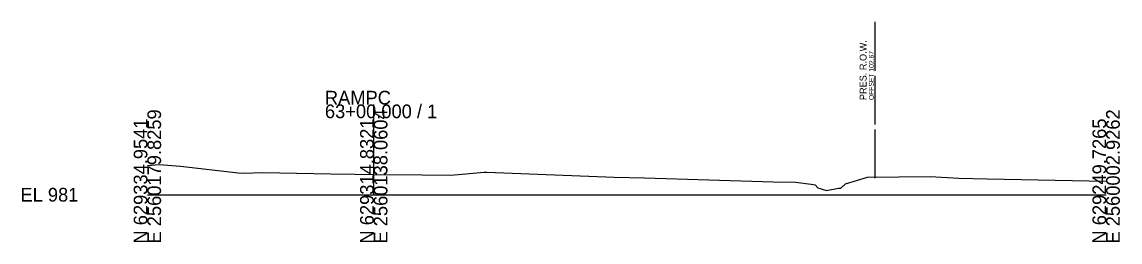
# Model space of a CAD drawing. Extents: x -985277 to -984049, y -985285 to -975702.
# Drawn here: x -984277.3 to -984052.4, y -983761.3 to -983716.3 of the extents above; entities that cross this region are included whole.
import ezdxf

# ---------------------------------------------------------------- set-up
doc = ezdxf.new("R2010")
doc.units = 0
for name, color, linetype in [('DESIGN - SHEET - Light Grid', 7, 'Continuous'), ('SURVEY - GROUND - Top of Rock Layer', 7, 'Continuous'), ('SURVEY - PROPERTY - ROW Lines', 7, 'Continuous'), ('SURVEY - PROPERTY - ROW Lines Text', 7, 'Continuous')]:
    doc.layers.add(name, color=color, linetype=linetype)

msp = doc.modelspace()

# ---------------------------------------------------------------- linework, layer by layer
at = {"layer": 'DESIGN - SHEET - Light Grid'}
for p, q in [((-984205.28, -983751.64), (-984205.28, -983733.17)), ((-984251.64, -983751.64), (-984205.28, -983751.64)), ((-984205.28, -983751.64), (-984055.28, -983751.64))]:
    msp.add_line(p, q, dxfattribs=at)
at = {"layer": 'SURVEY - GROUND - Top of Rock Layer'}
msp.add_lwpolyline([(-984251.64, -983745.64), (-984249.23, -983745.48), (-984244.85, -983745.78), (-984233.08, -983747.16), (-984232.01, -983747.24), (-984228.01, -983747.09), (-984214.08, -983747.37), (-984209.1, -983747.43), (-984205.28, -983747.47), (-984195.4, -983747.58), (-984189.53, -983747.67), (-984185.7, -983747.33), (-984182.67, -983747.05), (-984182.14, -983747.02), (-984156.03, -983748.06), (-984149.83, -983748.18), (-984123.46, -983749.01), (-984118.88, -983749.09), (-984115.68, -983749.45), (-984114.86, -983749.59), (-984114.35, -983750.25), (-984112.53, -983750.75), (-984110.09, -983750.33), (-984109.62, -983750.3), (-984108.68, -983749.4), (-984104.14, -983748.05), (-984091.32, -983747.94), (-984085.43, -983748.26), (-984079.68, -983748.4), (-984055.28, -983748.87)], dxfattribs=at)
at = {"layer": 'SURVEY - PROPERTY - ROW Lines'}
for p, q in [((-984102.61, -983726.27), (-984102.61, -983716.27)), ((-984102.61, -983737.27), (-984102.61, -983727.27)), ((-984102.61, -983748.27), (-984102.61, -983738.27))]:
    msp.add_line(p, q, dxfattribs=at)

# ---------------------------------------------------------------- texts
at = {"layer": 'DESIGN - SHEET - Light Grid'}
for s, p in [('RAMPC', (-984215.28, -983733.17)), ('63+00.000 / 1', (-984215.28, -983735.97)), ('EL 981', (-984277.64, -983753.04))]:
    msp.add_text(s, height=2.8, dxfattribs=at).set_placement(p)
for s, p in [('E 2560179.8259', (-984248.84, -983761.64)), ('E 2560138.0604', (-984202.48, -983761.64)), ('E 2560002.9262', (-984052.48, -983761.64)), ('N 629334.9541', (-984251.64, -983761.64)), ('N 629314.8321', (-984205.28, -983761.64)), ('N 629249.7265', (-984055.28, -983761.64))]:
    msp.add_text(s, height=2.8, rotation=90, dxfattribs=at).set_placement(p)
at = {"layer": 'SURVEY - PROPERTY - ROW Lines Text'}
for s, height, p in [('PRES. R.O.W. ', 1.4, (-984104.36, -983732.27)), ('OFFSET 102.67', 1, (-984102.86, -983732.27))]:
    msp.add_text(s, height=height, rotation=90, dxfattribs=at).set_placement(p)

doc.saveas('drawing.dxf')
